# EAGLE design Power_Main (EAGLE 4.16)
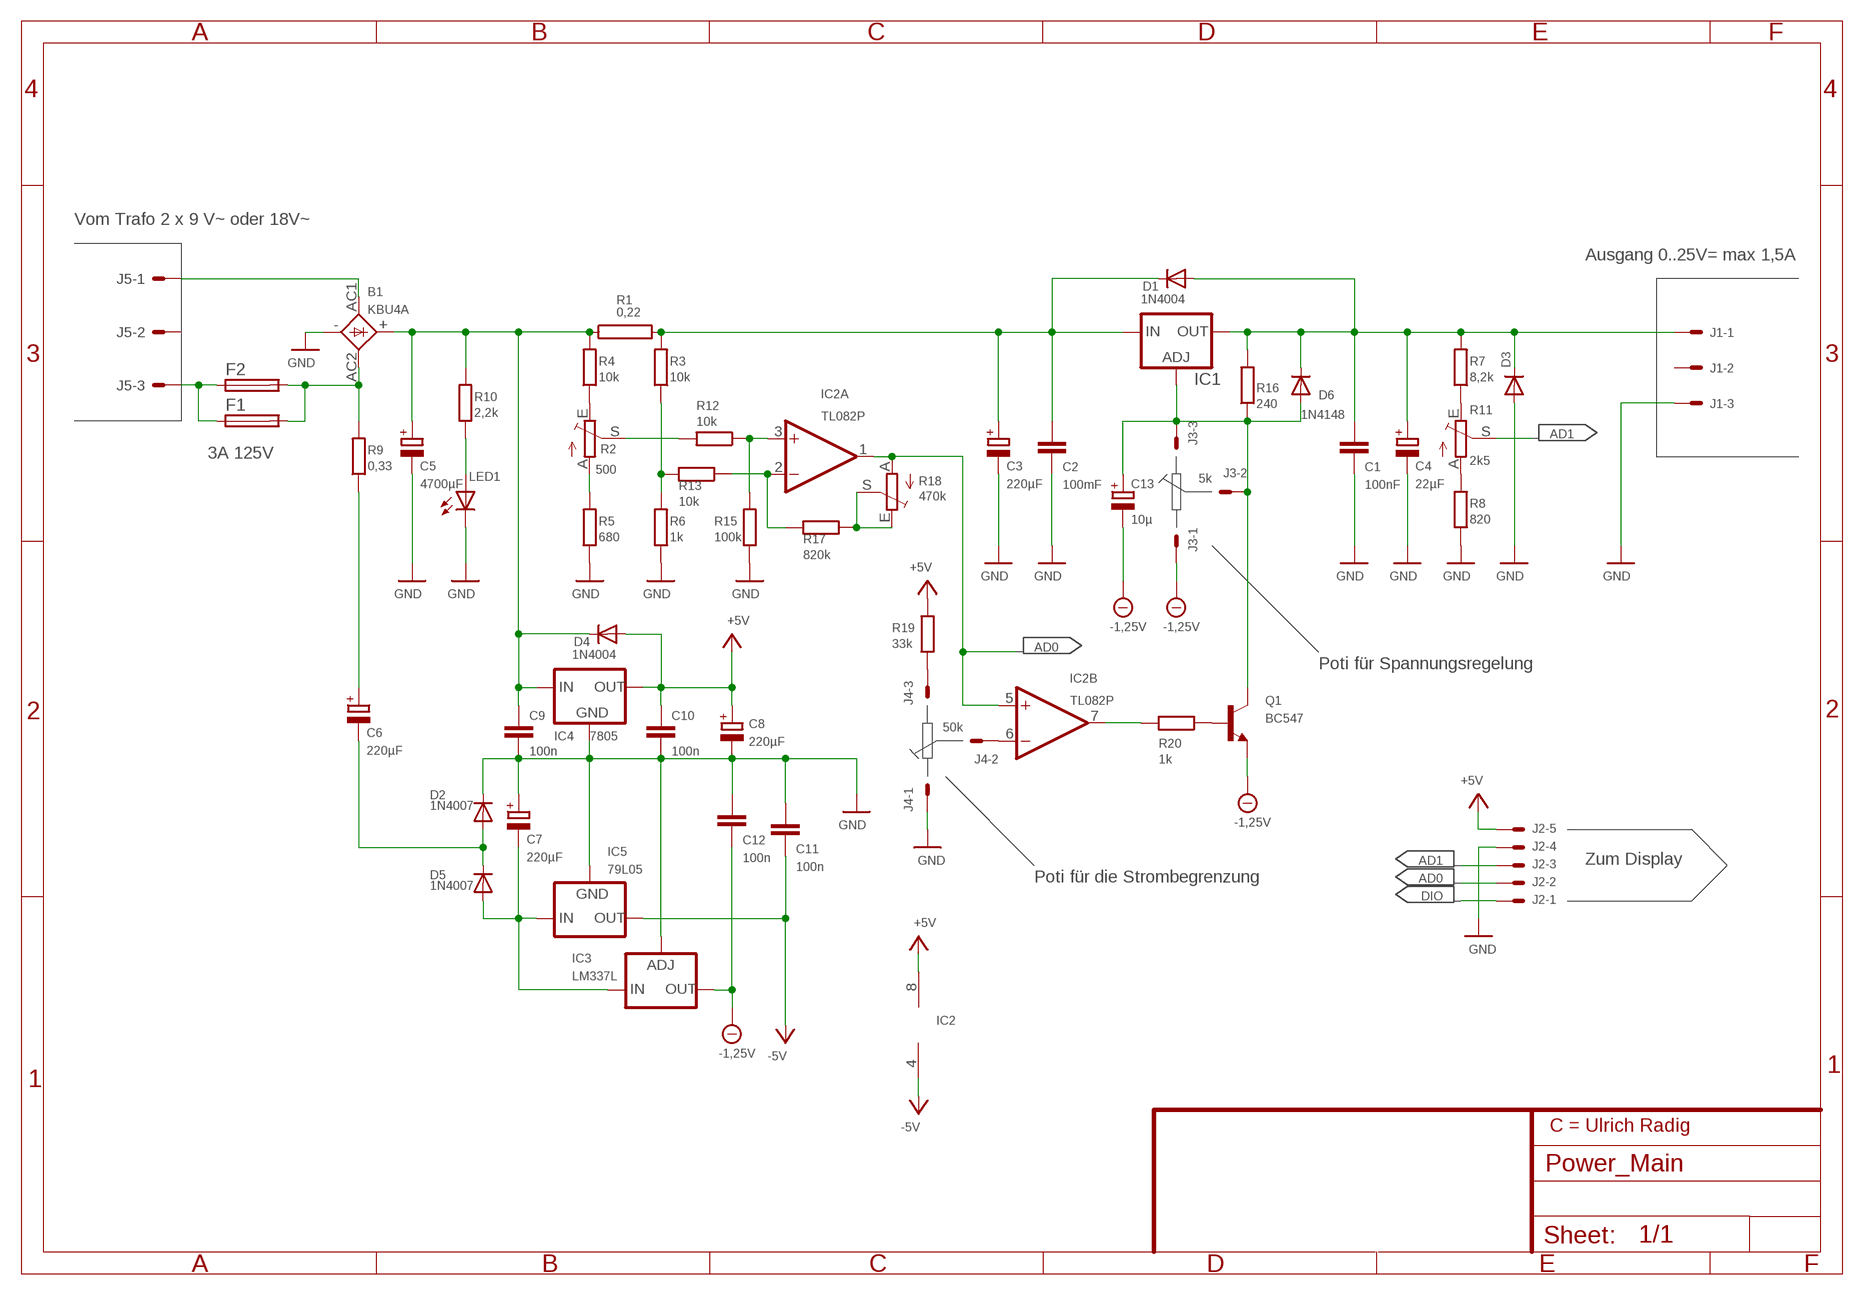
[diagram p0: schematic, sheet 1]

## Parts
B1  KBU4A  KBU  [KBU]
C1  100nF  C-EU025-024X044  [C025-024X044]
C2  100mF  C-EU025-024X044  [C025-024X044]
C3  220µF  CPOL-EUE3.5-8  [E3,5-8]
C4  22µF  CPOL-EUE3.5-8  [E3,5-8]
C5  4700µF  CPOL-EUE7.5-18  [E7,5-18]
C6  220µF  CPOL-EUE3.5-8  [E3,5-8]
C7  220µF  CPOL-EUE3.5-8  [E3,5-8]
C8  220µF  CPOL-EUE3.5-8  [E3,5-8]
C9  100n  C-EU025-024X044  [C025-024X044]
C10  100n  C-EU025-024X044  [C025-024X044]
C11  100n  C-EU025-024X044  [C025-024X044]
C12  100n  C-EU025-024X044  [C025-024X044]
C13  10µ  CPOL-EUE2-5  [E2-5]
D1  1N4004  [DO41-10]
D2  1N4007  1N4004  [DO41-10]
D3  1N4004  [DO41-10]
D4  1N4004  [DO41-10]
D5  1N4007  1N4004  [DO41-10]
D6  1N4148  [DO35-10]
F1  3A 125V  PICOFUSE  [PICOFUSE]
F2  PICOFUSE  [PICOFUSE]
IC1  LM317TS  [317TS]
IC2  TL082P  [DIL08]
IC3  LM337L  [337L]
IC4  7805  78XXS  [78XXS]
IC5  79L05  79LXX  [79LXX]
J1  22-27-2031-03  [6410-03]
J2  22-27-2051-05  [6410-05]
J3  22-27-2031-03  [6410-03]
J4  22-27-2031-03  [6410-03]
J5  22-27-2031-03  [6410-03]
LED1  LED3MM  [LED3MM]
Q1  BC547  [TO92]
R1  0,22  RKH208-8  [KH208-8]
R2  500  TRIM_EU-B64W  [B64W]
R3  10k  R-EU_0207/10  [0207/10]
R4  10k  R-EU_0207/10  [0207/10]
R5  680  R-EU_0207/10  [0207/10]
R6  1k  R-EU_0207/10  [0207/10]
R7  8,2k  R-EU_0207/10  [0207/10]
R8  820  R-EU_0207/10  [0207/10]
R9  0,33  R-EU_0309/12  [0309/12]
R10  2,2k  R-EU_0207/10  [0207/10]
R11  2k5  TRIM_EU-LI10  [LI10]
R12  10k  R-EU_0207/10  [0207/10]
R13  10k  R-EU_0207/10  [0207/10]
R15  100k  R-EU_0207/10  [0207/10]
R16  240  R-EU_0207/10  [0207/10]
R17  820k  R-EU_0207/10  [0207/10]
R18  470k  TRIM_EU-LI10  [LI10]
R19  33k  R-EU_0207/10  [0207/10]
R20  1k  R-EU_0207/10  [0207/10]

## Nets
+5V: C8.+ C10.1 D4.A IC2.8(P:V+) IC4.OUT J2.5 R19.2
-3V: C12.2 C13.- IC3.OUT J3.1 Q1.1(E) ; supply symbol labelled -1,25V
-5V: C11.2 IC2.4(P:V-) IC5.OUT
AD0: IC2.1(A:OUT) IC2.5(B:+IN) J2.2 R18.A
AD1: J2.3 R11.S
DIO: J2.1
GND: B1.- C1.2 C2.2 C3.- C4.- C5.- C7.+ C8.- C9.2 C10.2 C11.1 C12.1 D2.C D3.A IC3.ADJ IC4.GND IC5.GND J1.3 J2.4 J4.1 LED1.K(C) R5.1 R6.1 R8.1 R15.1
N$1: F1.1 F2.1 J5.3
N$2: C2.1 C3.+ D1.C IC1.3(IN) R1.2 R3.2
N$3: B1.AC1 J5.1
N$4: B1.AC2 F1.2 F2.2 R9.2
N$5: R3.1 R6.2 R13.2
N$6: B1.+ C5.+ C9.1 D4.C IC4.IN R1.1 R4.2 R10.2
N$7: C13.+ D6.A IC1.1(ADJ) J3.2 J3.3 Q1.3(C) R16.1
N$8: R2.E R4.1
N$9: R2.A R5.2
N$10: R2.S R12.2
N$11: C1.1 C4.+ D1.A D3.C D6.C IC1.2(OUT) J1.1 R7.2 R16.2
N$12: R7.1 R11.E
N$13: C6.+ R9.1
N$14: R8.2 R11.A
N$15: IC2.3(A:+IN) R12.1 R15.2
N$16: C6.- D2.A D5.C
N$17: C7.- D5.A IC3.IN IC5.IN
N$18: IC2.6(B:-IN) J4.2
N$19: J4.3 R19.1
N$20: IC2.2(A:-IN) R13.1 R17.2
N$21: R17.1 R18.E R18.S
N$22: IC2.7(B:OUT) R20.2
N$23: Q1.2(B) R20.1
N$29: LED1.A R10.1
Unconnected: J1.2 J5.2

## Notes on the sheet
- Vom Trafo 2 x 9 V~ oder 18V~
- Ausgang 0..25V= max 1,5A
- 5k
- Poti für Spannungsregelung
- 50k
- Zum Display
- Poti für die Strombegrenzung
- IC2
- C = Ulrich Radig

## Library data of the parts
B1 = rectifier:KBU: DIOTEC RECTIFIER
C1 C2 C9-C12 = rcl:C-EU: CAPACITOR, European symbol
C3-C8 C13 = rcl:CPOL-EU: POLARIZED CAPACITOR, European symbol
D1-D5 = diode:1N4004: DIODE
D6 = diode:1N4148: DIODE
F1 F2 = fuse:PICOFUSE: PICOFUSE
IC1 = v-reg:LM317TS: VOLTAGE REGULATOR
IC2 = linear:TL082: OP AMP
IC3 = v-reg:LM337L: VOLTAGE REGULATOR
IC4 = v-reg:78XXS: VOLTAGE REGULATOR
IC5 = v-reg:79LXX: VOLTAGE REGULATOR
J1 J3-J5 = con-molex:22-?-03: CONNECTOR wire to board 2.54 mm (.1 inch) pitch header
J2 = con-molex:22-?-05: CONNECTOR wire to board 2.54 mm (.1 inch) pitch header
LED1 = led:LED: LED
Q1 = transistor-npn:BC547*: NPN Transistor
R1 = resistor-power:R: Power Resitor
R2 R11 R18 = pot:TRIM_EU-: POTENTIOMETER
R3-R10 R12 R13 R15-R17 R19 R20 = rcl:R-EU_: RESISTOR, European symbol

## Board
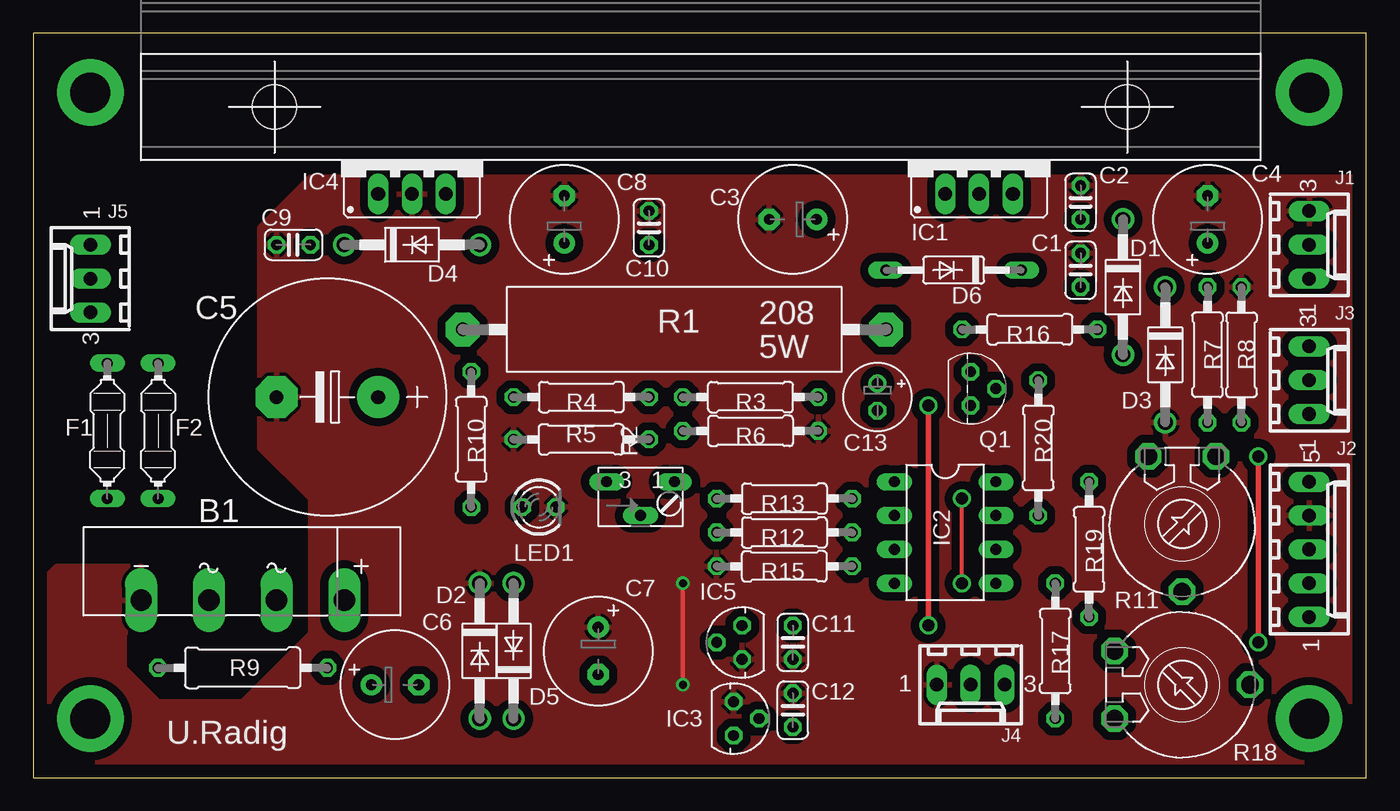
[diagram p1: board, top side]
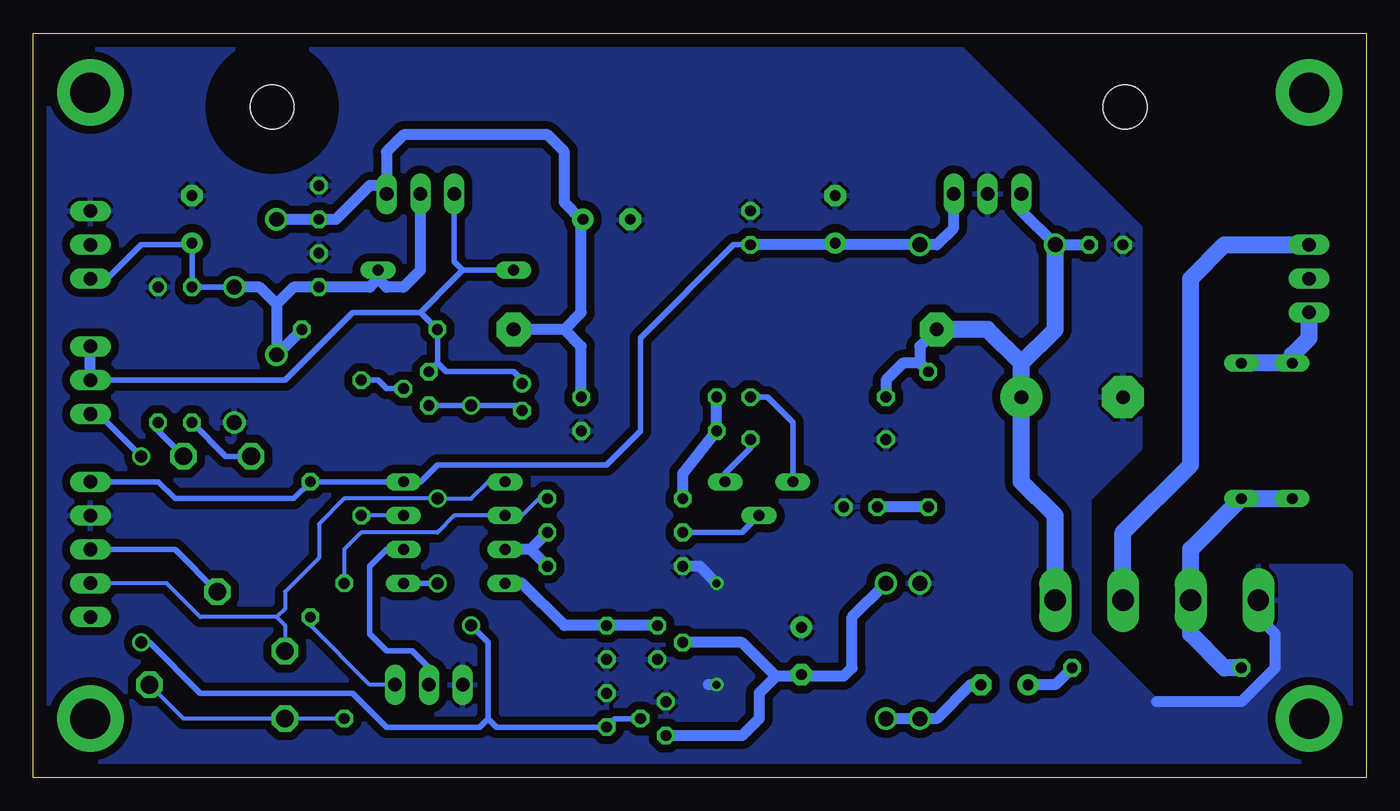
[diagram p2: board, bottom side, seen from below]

Size 100 x 55.86 mm. Coordinates in mm from the lower left corner, seen from the top.
Outline: 0,55.86 0,0 100,0 100,55.86 0,55.86
Copper layers (1*16): Top 0.035mm / dielectric 1.5mm / Bottom 0.035mm
Design rules "default": minimum track width 10mil, minimum drill 24mil, track to track 8mil, track to pad 8mil, pad to pad 8mil, via to via 8mil, smd to smd 8mil, copper to edge 40mil, drill to drill 8mil, minimum pad ring 10mil, minimum via ring 8mil, stop-mask expansion 4mil, vias tented up to drill 0mil, thermal gap 10mil

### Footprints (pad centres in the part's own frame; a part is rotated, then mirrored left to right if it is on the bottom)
KBU = drill 1.6 long: + -7.62,2.54; - 7.62,2.54; AC1 -2.54,2.54; AC2 2.54,2.54
C025-024X044 = drill 0.813 octagon: 1 -1.27,0; 2 1.27,0
E3,5-8 = drill 0.813 pad 1.6 round: + -1.778,0 | drill 0.813 pad 1.6 octagon: - 1.778,0
E7,5-18 = drill 1.016 pad 3.15 round: + -3.81,0 | drill 1.016 pad 3.15 octagon: - 3.81,0
E2-5 = drill 0.813 pad 1.27 round: + -1.016,0 | drill 0.813 pad 1.27 octagon: - 1.016,0
DO41-10 = drill 1.118 round: A 5.08,0; C -5.08,0
DO35-10 = drill 0.813 long: A 5.08,0; C -5.08,0
PICOFUSE = drill 0.813 long: 1 -5.08,0; 2 5.08,0
317TS = drill 1.016 long: 1 -2.54,-2.54; 2 0,-2.54; 3 2.54,-2.54
DIL08 = drill 0.813 long: 1 -3.81,-3.81; 2 -1.27,-3.81; 3 1.27,-3.81; 4 3.81,-3.81; 5 3.81,3.81; 6 1.27,3.81; 7 -1.27,3.81; 8 -3.81,3.81
337L = drill 0.813 octagon: ADJ -1.27,0; IN 1.27,0; OUT 0,1.905
78XXS = drill 1.016 long: GND 0,-2.54; IN -2.54,-2.54; OUT 2.54,-2.54
79LXX = drill 0.813 octagon: GND -1.27,0; IN 0,1.905; OUT 1.27,0
6410-03 = drill 1.016 long: 1 2.54,0; 2 0,0; 3 -2.54,0
6410-05 = drill 1.016 long: 1 5.08,0; 2 2.54,0; 3 0,0; 4 -2.54,0; 5 -5.08,0
LED3MM = drill 0.813 octagon: A -1.27,0; K 1.27,0
TO92 = drill 0.813 octagon: 1 1.27,0; 2 0,1.905; 3 -1.27,0
KH208-8 = drill 1.016 pad 2.54 octagon: 1 -15.875,0; 2 15.875,0
B64W = drill 0.813 long: A 2.54,0; E -2.54,0; S 0,-2.54
0207/10 = drill 0.813 octagon: 1 -5.08,0; 2 5.08,0
0309/12 = drill 0.813 octagon: 1 -6.35,0; 2 6.35,0
LI10 = drill 1.321 octagon: A -2.54,-5.08; E 2.54,-5.08; S 0,5.08
SK96/84 = hole 3.302: -31.902,3.988; 32.08,3.988

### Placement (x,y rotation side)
B1  15.71,15.86 180 top
C1  78.57,38.09 90 top
C2  78.57,43.16 90 top
C3  56.98,41.89 180 top
C4  88.1,41.89 90 top
C5  22.06,28.56 180 top
C6  27.14,6.97 0 top
C7  42.38,9.51 270 top
C8  39.84,41.89 90 top
C9  19.52,39.99 180 top
C10  46.19,41.26 90 top
C11  56.98,10.14 90 top
C12  56.98,5.07 270 top
C13  63.34,28.56 270 top
D1  81.75,36.81 270 top
D2  33.49,9.51 270 top
D3  84.92,31.73 270 top
D4  28.41,39.99 0 top
D5  36.03,9.51 90 top
D6  69.05,38.09 180 top
F1  5.55,26.02 270 top
F2  9.36,26.02 270 top
IC1  70.95,46.34 0 top
IC2  68.41,18.4 270 top
IC3  52.54,4.43 270 top
IC4  28.41,46.34 0 top
IC5  53.18,10.14 90 top
J1  95.72,39.99 270 top
J2  95.72,17.13 270 top
J3  95.72,29.83 270 top
J4  70.32,6.97 180 top
J5  4.28,37.45 90 top
LED1  37.94,20.3 0 top
Q1  70.32,29.2 270 top
R1  48.09,33.64 0 top
R2  45.55,22.21 0 top
R3  53.81,28.56 0 top
R4  41.11,28.56 180 top
R5  41.11,25.38 0 top
R6  53.81,26.02 180 top
R7  88.1,31.73 90 top
R8  90.64,31.73 270 top
R9  15.71,8.24 180 top
R10  32.86,25.38 90 top
R11  86.19,19.04 180 top
R12  56.35,18.4 180 top
R13  56.35,20.94 180 top
R15  56.35,15.86 0 top
R16  74.77,33.64 0 top
R17  76.67,9.51 90 top
R18  86.19,6.97 270 top
R19  79.21,17.13 90 top
R20  75.4,24.75 270 top
U$1  [SK96/84]  50,46.34 0 top

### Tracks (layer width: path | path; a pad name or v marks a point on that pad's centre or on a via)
+5V
  Bottom 0.305: 39.84,39.99 C8.+
  Bottom 0.406: C10.1 47.46,39.99 54.45,33.01 54.45,26.02 56.98,23.48 69.68,23.48 70.95,22.21 IC2.8 R19.2 80.48,20.94 89.37,20.94 90.64,22.21 J2.5
  Bottom 0.813: IC4.OUT 30.95,41.26 32.22,39.99 D4.A 39.84,39.99 C10.1
-3V  (via drill 0.9)
  Top 0.406: v91.91,10.14 v91.91,24.11 | v67.14,11.41 v67.14,27.93
  Bottom 0.406: J3.1 95.08,27.29 v91.91,24.11 | v91.91,10.14 91.27,10.14 87.46,6.33 76.03,6.33 73.49,3.79 66.51,3.79 65.88,4.43 | Q1.1 v67.14,27.93 63.34,27.93 63.59,27.54 C13.- | v67.14,11.41 65.88,10.14 65.88,4.43 | 65.88,4.43 65.24,3.79 C12.2 56.35,4.43 IC3.OUT
-5V
  Bottom 0.813: IC2.4 63.34,14.59 60.16,11.41 C11.2 IC5.OUT
AD0  (via drill 0.9)
  Top 0.305: v69.68,14.59 v69.68,20.94
  Bottom 0.305: 81.75,12.05 81.11,12.68 81.11,13.96 78.57,16.5 78.57,19.04 76.67,20.94 v69.68,20.94 67.14,20.94 65.88,22.21 IC2.1 | 81.75,12.05 87.46,12.05 90,14.59 J2.2 | 81.75,12.05 81.11,11.41 R18.A
  Bottom 0.406: v69.68,14.59 IC2.5
AD1
  Bottom 0.406: R11.S 89.37,17.13 J2.3
GND  (via drill 0.6)
  Top 0.305: v48.73,6.97 v48.73,14.59
  Bottom 0.813: B1.- 8.09,12.05 6.82,10.78 6.82,8.24 9.36,5.7 15.71,5.7 | R15.1 50,15.86 v48.73,14.59 | v48.73,6.97 49.37,6.97
  pour Bottom (isolate 0.61): 99.53,55.23 99.53,0.62 0.47,0.62 0.47,14.59 1.74,15.86 8.09,15.86 8.09,12.05 6.82,10.78 6.82,8.24 9.36,5.7 15.71,5.7 20.79,10.78 20.79,20.94 16.98,24.75 16.98,41.26 30.95,55.23
  pour Top (isolate 0.61): 99.53,45.07 99.53,0.62 0.47,0.62 0.47,14.59 1.74,15.86 8.09,15.86 8.09,12.05 6.82,10.78 6.82,8.24 9.36,5.7 15.71,5.7 20.79,10.78 20.79,20.94 16.98,24.75 16.98,41.26 20.79,45.07
N$1
  Bottom 1.27: F2.1 F1.1 5.55,31.73 4.28,33.01 J5.3
N$2
  Bottom 0.406: C2.1 D1.C
  Bottom 0.813: R3.2 58.89,32.37 60.16,33.64 | D1.C C2.1 77.3,41.89 74.77,44.44 73.49,44.44 IC1.3 73.49,46.98 72.22,48.24 61.43,48.24 60.16,46.98 60.16,43.16 58.89,41.89 | 58.89,41.89 C3.+ | R1.2 62.7,33.64 60.16,33.64 | 60.16,33.64 58.89,34.91 58.89,41.89
N$3
  Bottom 1.27: B1.AC1 18.25,18.4 13.17,23.48 13.17,37.45 10.63,39.99 J5.1
N$4
  Bottom 1.27: R9.2 10.63,8.24 13.17,10.78 B1.AC2 13.17,17.13 F2.2 F1.2
N$5
  Bottom 0.813: R3.1 R6.2 51.27,22.84 R13.2
N$6
  Bottom 0.813: R1.1 33.49,32.37 33.49,31.1 | C9.1 D4.C 25.87,42.53 IC4.IN | R4.2 36.03,29.83 34.76,31.1 33.49,31.1 | 33.49,31.1 R10.2
  Bottom 1.27: B1.+ 23.33,19.67 25.87,22.21 C5.+ 25.87,31.1 | 25.87,31.1 28.41,33.64 R1.1 | D4.C 23.33,33.64 25.87,31.1
N$7
  Bottom 0.406: J3.2 83.02,29.83 81.11,29.83 76.03,34.91 70.95,34.91 | 70.95,34.91 68.41,37.45 67.78,38.09 | 70.95,34.91 R16.1 69.68,31.1 | 69.68,31.1 Q1.3 | C13.+ 63.08,29.58 63.97,30.46 69.05,30.46 69.68,31.1 | 67.78,38.09 D6.A | 67.78,38.09 68.41,38.72 IC1.1
  Bottom 0.813: J3.2 J3.3
N$8
  Bottom 0.406: R2.E 43.02,26.66 44.92,28.56 R4.1
N$9
  Bottom 0.406: R2.A 48.09,22.84 46.19,24.75 R5.2
N$10
  Bottom 0.406: R12.2 46.83,18.4 R2.S
N$11
  Bottom 0.406: J1.1 94.45,37.45 91.91,39.99 88.1,39.99 | 88.1,39.99 C4.+ | 88.1,39.99 R7.2 D3.C
  Bottom 0.813: D3.C 83.02,36.81 81.75,35.55 | 81.75,35.55 D1.A R16.2 | IC1.2 70.95,38.09 72.22,36.81 73.49,36.81 74.13,37.45 | 74.13,37.45 D6.C | 74.13,37.45 74.77,36.81 C1.1 80.48,36.81 81.75,35.55
N$12
  Bottom 0.406: R7.1 85.56,24.11 R11.E
N$13
  Bottom 0.813: R9.1 23.33,6.97 C6.+
N$14
  Bottom 0.406: R8.2 90.64,26.02 R11.A
N$15
  Bottom 0.813: 62.7,17.13 R12.1 | 62.7,17.13 IC2.3 | R15.2 62.7,17.13
N$16
  Bottom 0.813: C6.- 29.68,6.97 32.22,4.43 D2.A D5.C
N$17
  Bottom 0.813: D5.A 38.57,12.05 38.57,8.24 39.2,7.61 42.38,7.61 | 42.51,7.73 C7.- 41.87,7.73 42.38,7.61 | 42.51,7.73 42.89,7.73 | 42.38,7.61 42.51,7.73 | 42.38,7.61 44.29,7.61 | 44.29,7.61 46.83,10.14 IC5.IN | 44.29,7.61 45.55,6.33 45.55,4.43 46.83,3.16 IC3.IN
N$18
  Bottom 0.406: IC2.6 73.49,17.13 74.77,15.86 74.77,10.78 73.49,9.51 71.59,9.51 70.32,8.24 J4.2
N$19
  Bottom 0.305: R19.1 79.21,11.41 74.77,6.97 J4.3
N$20
  Bottom 0.305: R17.2 76.67,17.13 75.4,18.4 69.68,18.4 68.41,19.67 IC2.2 63.34,19.67 62.06,20.94 R13.1
N$21
  Bottom 0.305: R18.S 88.73,4.43 R18.E R17.1
N$22
  Bottom 0.305: IC2.7 R20.2
N$23
  Bottom 0.406: Q1.2 73.49,29.2 74.13,29.83 R20.1
N$25  (via drill 3 pad 5)
  other vias: 95.72,4.43
N$26  (via drill 3 pad 5)
  other vias: 4.28,4.43
N$27  (via drill 3 pad 5)
  other vias: 4.28,51.42
N$28  (via drill 3 pad 5)
  other vias: 95.72,51.42
N$29
  Bottom 0.813: R10.1 LED1.A

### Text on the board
tPlace: U.Radig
